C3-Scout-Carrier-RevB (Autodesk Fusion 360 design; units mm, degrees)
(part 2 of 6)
sketch "Socket solder tails profiles" plane through (0, 0, -3.2) normal (0, 0, 1) x axis (1, 0, 0)
  line L1 (-3.56, -9.14) -> (-4.06, -9.14)
  line L2 (-3.56, -8.64) -> (-3.56, -9.14)
  line L3 (-4.06, -8.64) -> (-3.56, -8.64)
  line L4 (-4.06, -9.14) -> (-4.06, -8.64)
  line L5 (-3.56, -6.6) -> (-4.06, -6.6)
  line L6 (-3.56, -6.1) -> (-3.56, -6.6)
  line L7 (-4.06, -6.1) -> (-3.56, -6.1)
  line L8 (-4.06, -6.6) -> (-4.06, -6.1)
  line L9 (-3.56, -4.06) -> (-4.06, -4.06)
  line L10 (-3.56, -3.56) -> (-3.56, -4.06)
  line L11 (-4.06, -3.56) -> (-3.56, -3.56)
  line L12 (-4.06, -4.06) -> (-4.06, -3.56)
  line L13 (-3.56, -1.52) -> (-4.06, -1.52)
  line L14 (-3.56, -1.02) -> (-3.56, -1.52)
  line L15 (-4.06, -1.02) -> (-3.56, -1.02)
  line L16 (-4.06, -1.52) -> (-4.06, -1.02)
  line L17 (-3.56, 1.02) -> (-4.06, 1.02)
  line L18 (-3.56, 1.52) -> (-3.56, 1.02)
  line L19 (-4.06, 1.52) -> (-3.56, 1.52)
  line L20 (-4.06, 1.02) -> (-4.06, 1.52)
  line L21 (-3.56, 3.56) -> (-4.06, 3.56)
  line L22 (-3.56, 4.06) -> (-3.56, 3.56)
  line L23 (-4.06, 4.06) -> (-3.56, 4.06)
  line L24 (-4.06, 3.56) -> (-4.06, 4.06)
  line L25 (-3.56, 6.1) -> (-4.06, 6.1)
  line L26 (-3.56, 6.6) -> (-3.56, 6.1)
  line L27 (-4.06, 6.6) -> (-3.56, 6.6)
  line L28 (-4.06, 6.1) -> (-4.06, 6.6)
  line L29 (-3.56, 8.64) -> (-4.06, 8.64)
  line L30 (-3.56, 9.14) -> (-3.56, 8.64)
  line L31 (-4.06, 9.14) -> (-3.56, 9.14)
  line L32 (-4.06, 8.64) -> (-4.06, 9.14)
  line L33 (4.06, -9.14) -> (3.56, -9.14)
  line L34 (4.06, -8.64) -> (4.06, -9.14)
  line L35 (3.56, -8.64) -> (4.06, -8.64)
  line L36 (3.56, -9.14) -> (3.56, -8.64)
  line L37 (4.06, -6.6) -> (3.56, -6.6)
  line L38 (4.06, -6.1) -> (4.06, -6.6)
  line L39 (3.56, -6.1) -> (4.06, -6.1)
  line L40 (3.56, -6.6) -> (3.56, -6.1)
  line L41 (4.06, -4.06) -> (3.56, -4.06)
  line L42 (4.06, -3.56) -> (4.06, -4.06)
  line L43 (3.56, -3.56) -> (4.06, -3.56)
  line L44 (3.56, -4.06) -> (3.56, -3.56)
  line L45 (4.06, -1.52) -> (3.56, -1.52)
  line L46 (4.06, -1.02) -> (4.06, -1.52)
  line L47 (3.56, -1.02) -> (4.06, -1.02)
  line L48 (3.56, -1.52) -> (3.56, -1.02)
  line L49 (4.06, 1.02) -> (3.56, 1.02)
  line L50 (4.06, 1.52) -> (4.06, 1.02)
  line L51 (3.56, 1.52) -> (4.06, 1.52)
  line L52 (3.56, 1.02) -> (3.56, 1.52)
  line L53 (4.06, 3.56) -> (3.56, 3.56)
  line L54 (4.06, 4.06) -> (4.06, 3.56)
  line L55 (3.56, 4.06) -> (4.06, 4.06)
  line L56 (3.56, 3.56) -> (3.56, 4.06)
  line L57 (4.06, 6.1) -> (3.56, 6.1)
  line L58 (4.06, 6.6) -> (4.06, 6.1)
  line L59 (3.56, 6.6) -> (4.06, 6.6)
  line L60 (3.56, 6.1) -> (3.56, 6.6)
  line L61 (4.06, 8.64) -> (3.56, 8.64)
  line L62 (4.06, 9.14) -> (4.06, 8.64)
  line L63 (3.56, 9.14) -> (4.06, 9.14)
  line L64 (3.56, 8.64) -> (3.56, 9.14)
extrude "Extrude5" new body sketch "Socket solder tails profiles" along normal blind 3.3
work_plane "WorkPlane1" AlongDistance 0.8 ExtraOffset 0
sketch "L293D molded body profile" plane through (0, 0, 0.8) normal (0, 0, 1) x axis (1, 0, 0)
  line L1 (3.2, -9.8) -> (-3.2, -9.8)
  line L2 (3.2, 9.8) -> (3.2, -9.8)
  line L3 (-3.2, 9.8) -> (3.2, 9.8)
  line L4 (-3.2, -9.8) -> (-3.2, 9.8)
extrude "Extrude1" new body sketch "L293D molded body profile" along normal blind 3.6
work_plane "WorkPlane2" AlongDistance 3.7 ExtraOffset 0
sketch "Orientation notch profile" plane through (0, 0, 3.7) normal (0, 0, 1) x axis (1, 0, 0)
  circle C1 centre (0, 9.8) radius 1.1
extrude "Extrude2" cut sketch "Orientation notch profile" along normal blind 0.7
work_plane "WorkPlane3" AlongDistance 4.4 ExtraOffset 0
sketch "Pin one dot profile" plane through (0, 0, 4.4) normal (0, 0, 1) x axis (1, 0, 0)
  circle C1 centre (-2.1, 7.8) radius 0.38
extrude "Extrude3" new body sketch "Pin one dot profile" along normal blind 0.025
work_plane "WorkPlane4" AlongDistance -2.5 ExtraOffset 0
sketch "DIP vertical leads profiles" plane through (0, 0, -2.5) normal (0, 0, 1) x axis (1, 0, 0)
  line L1 (-3.61, -9.14) -> (-4.01, -9.14)
  line L2 (-3.61, -8.64) -> (-3.61, -9.14)
  line L3 (-4.01, -8.64) -> (-3.61, -8.64)
  line L4 (-4.01, -9.14) -> (-4.01, -8.64)
  line L5 (-3.61, -6.6) -> (-4.01, -6.6)
  line L6 (-3.61, -6.1) -> (-3.61, -6.6)
  line L7 (-4.01, -6.1) -> (-3.61, -6.1)
  line L8 (-4.01, -6.6) -> (-4.01, -6.1)
  line L9 (-3.61, -4.06) -> (-4.01, -4.06)
  line L10 (-3.61, -3.56) -> (-3.61, -4.06)
  line L11 (-4.01, -3.56) -> (-3.61, -3.56)
  line L12 (-4.01, -4.06) -> (-4.01, -3.56)
  line L13 (-3.61, -1.52) -> (-4.01, -1.52)
  line L14 (-3.61, -1.02) -> (-3.61, -1.52)
  line L15 (-4.01, -1.02) -> (-3.61, -1.02)
  line L16 (-4.01, -1.52) -> (-4.01, -1.02)
  line L17 (-3.61, 1.02) -> (-4.01, 1.02)
  line L18 (-3.61, 1.52) -> (-3.61, 1.02)
  line L19 (-4.01, 1.52) -> (-3.61, 1.52)
  line L20 (-4.01, 1.02) -> (-4.01, 1.52)
  line L21 (-3.61, 3.56) -> (-4.01, 3.56)
  line L22 (-3.61, 4.06) -> (-3.61, 3.56)
  line L23 (-4.01, 4.06) -> (-3.61, 4.06)
  line L24 (-4.01, 3.56) -> (-4.01, 4.06)
  line L25 (-3.61, 6.1) -> (-4.01, 6.1)
  line L26 (-3.61, 6.6) -> (-3.61, 6.1)
  line L27 (-4.01, 6.6) -> (-3.61, 6.6)
  line L28 (-4.01, 6.1) -> (-4.01, 6.6)
  line L29 (-3.61, 8.64) -> (-4.01, 8.64)
  line L30 (-3.61, 9.14) -> (-3.61, 8.64)
  line L31 (-4.01, 9.14) -> (-3.61, 9.14)
  line L32 (-4.01, 8.64) -> (-4.01, 9.14)
  line L33 (4.01, -9.14) -> (3.61, -9.14)
  line L34 (4.01, -8.64) -> (4.01, -9.14)
  line L35 (3.61, -8.64) -> (4.01, -8.64)
  line L36 (3.61, -9.14) -> (3.61, -8.64)
  line L37 (4.01, -6.6) -> (3.61, -6.6)
  line L38 (4.01, -6.1) -> (4.01, -6.6)
  line L39 (3.61, -6.1) -> (4.01, -6.1)
  line L40 (3.61, -6.6) -> (3.61, -6.1)
  line L41 (4.01, -4.06) -> (3.61, -4.06)
  line L42 (4.01, -3.56) -> (4.01, -4.06)
  line L43 (3.61, -3.56) -> (4.01, -3.56)
  line L44 (3.61, -4.06) -> (3.61, -3.56)
  line L45 (4.01, -1.52) -> (3.61, -1.52)
  line L46 (4.01, -1.02) -> (4.01, -1.52)
  line L47 (3.61, -1.02) -> (4.01, -1.02)
  line L48 (3.61, -1.52) -> (3.61, -1.02)
  line L49 (4.01, 1.02) -> (3.61, 1.02)
  line L50 (4.01, 1.52) -> (4.01, 1.02)
  line L51 (3.61, 1.52) -> (4.01, 1.52)
  line L52 (3.61, 1.02) -> (3.61, 1.52)
  line L53 (4.01, 3.56) -> (3.61, 3.56)
  line L54 (4.01, 4.06) -> (4.01, 3.56)
  line L55 (3.61, 4.06) -> (4.01, 4.06)
  line L56 (3.61, 3.56) -> (3.61, 4.06)
  line L57 (4.01, 6.1) -> (3.61, 6.1)
  line L58 (4.01, 6.6) -> (4.01, 6.1)
  line L59 (3.61, 6.6) -> (4.01, 6.6)
  line L60 (3.61, 6.1) -> (3.61, 6.6)
  line L61 (4.01, 8.64) -> (3.61, 8.64)
  line L62 (4.01, 9.14) -> (4.01, 8.64)
  line L63 (3.61, 9.14) -> (4.01, 9.14)
  line L64 (3.61, 8.64) -> (3.61, 9.14)
extrude "Extrude4" new body sketch "DIP vertical leads profiles" along normal blind 4.3
work_plane "WorkPlane5" AlongDistance 1.5 ExtraOffset 0
sketch "DIP lead shoulders profiles" plane through (0, 0, 1.5) normal (0, 0, 1) x axis (1, 0, 0)
  line L1 (-2.7, -9.14) -> (-4.01, -9.14)
  line L2 (-2.7, -8.64) -> (-2.7, -9.14)
  line L3 (-4.01, -8.64) -> (-2.7, -8.64)
  line L4 (-4.01, -9.14) -> (-4.01, -8.64)
  line L5 (-2.7, -6.6) -> (-4.01, -6.6)
  line L6 (-2.7, -6.1) -> (-2.7, -6.6)
  line L7 (-4.01, -6.1) -> (-2.7, -6.1)
  line L8 (-4.01, -6.6) -> (-4.01, -6.1)
  line L9 (-2.7, -4.06) -> (-4.01, -4.06)
  line L10 (-2.7, -3.56) -> (-2.7, -4.06)
  line L11 (-4.01, -3.56) -> (-2.7, -3.56)
  line L12 (-4.01, -4.06) -> (-4.01, -3.56)
  line L13 (-2.7, -1.52) -> (-4.01, -1.52)
  line L14 (-2.7, -1.02) -> (-2.7, -1.52)
  line L15 (-4.01, -1.02) -> (-2.7, -1.02)
  line L16 (-4.01, -1.52) -> (-4.01, -1.02)
  line L17 (-2.7, 1.02) -> (-4.01, 1.02)
  line L18 (-2.7, 1.52) -> (-2.7, 1.02)
  line L19 (-4.01, 1.52) -> (-2.7, 1.52)
  line L20 (-4.01, 1.02) -> (-4.01, 1.52)
  line L21 (-2.7, 3.56) -> (-4.01, 3.56)
  line L22 (-2.7, 4.06) -> (-2.7, 3.56)
  line L23 (-4.01, 4.06) -> (-2.7, 4.06)
  line L24 (-4.01, 3.56) -> (-4.01, 4.06)
  line L25 (-2.7, 6.1) -> (-4.01, 6.1)
  line L26 (-2.7, 6.6) -> (-2.7, 6.1)
  line L27 (-4.01, 6.6) -> (-2.7, 6.6)
  line L28 (-4.01, 6.1) -> (-4.01, 6.6)
  line L29 (-2.7, 8.64) -> (-4.01, 8.64)
  line L30 (-2.7, 9.14) -> (-2.7, 8.64)
  line L31 (-4.01, 9.14) -> (-2.7, 9.14)
  line L32 (-4.01, 8.64) -> (-4.01, 9.14)
  line L33 (4.01, -9.14) -> (2.7, -9.14)
  line L34 (4.01, -8.64) -> (4.01, -9.14)
  line L35 (2.7, -8.64) -> (4.01, -8.64)
  line L36 (2.7, -9.14) -> (2.7, -8.64)
  line L37 (4.01, -6.6) -> (2.7, -6.6)
  line L38 (4.01, -6.1) -> (4.01, -6.6)
  line L39 (2.7, -6.1) -> (4.01, -6.1)
  line L40 (2.7, -6.6) -> (2.7, -6.1)
  line L41 (4.01, -4.06) -> (2.7, -4.06)
  line L42 (4.01, -3.56) -> (4.01, -4.06)
  line L43 (2.7, -3.56) -> (4.01, -3.56)
  line L44 (2.7, -4.06) -> (2.7, -3.56)
  line L45 (4.01, -1.52) -> (2.7, -1.52)
  line L46 (4.01, -1.02) -> (4.01, -1.52)
  line L47 (2.7, -1.02) -> (4.01, -1.02)
  line L48 (2.7, -1.52) -> (2.7, -1.02)
  line L49 (4.01, 1.02) -> (2.7, 1.02)
  line L50 (4.01, 1.52) -> (4.01, 1.02)
  line L51 (2.7, 1.52) -> (4.01, 1.52)
  line L52 (2.7, 1.02) -> (2.7, 1.52)
  line L53 (4.01, 3.56) -> (2.7, 3.56)
  line L54 (4.01, 4.06) -> (4.01, 3.56)
  line L55 (2.7, 4.06) -> (4.01, 4.06)
  line L56 (2.7, 3.56) -> (2.7, 4.06)
  line L57 (4.01, 6.1) -> (2.7, 6.1)
  line L58 (4.01, 6.6) -> (4.01, 6.1)
  line L59 (2.7, 6.6) -> (4.01, 6.6)
  line L60 (2.7, 6.1) -> (2.7, 6.6)
  line L61 (4.01, 8.64) -> (2.7, 8.64)
  line L62 (4.01, 9.14) -> (4.01, 8.64)
  line L63 (2.7, 9.14) -> (4.01, 9.14)
  line L64 (2.7, 8.64) -> (2.7, 9.14)
extrude "Extrude5" new body sketch "DIP lead shoulders profiles" along normal blind 0.3
sketch "Holder floor profile" plane through (0, 0, 0) normal (0, 0, 1) x axis (1, 0, 0)
  line L1 (11, -39) -> (-11, -39)
  line L2 (11, 39) -> (11, -39)
  line L3 (-11, 39) -> (11, 39)
  line L4 (-11, -39) -> (-11, 39)
extrude "Extrude1" new body sketch "Holder floor profile" along normal blind 2
work_plane "WorkPlane1" AlongDistance 2 ExtraOffset 0
sketch "Holder side lip profile" plane through (0, 0, 2) normal (0, 0, 1) x axis (1, 0, 0)
  line L1 (-9.8, -39) -> (-11, -39)
  line L2 (-9.8, 39) -> (-9.8, -39)
  line L3 (-11, 39) -> (-9.8, 39)
  line L4 (-11, -39) -> (-11, 39)
extrude "Extrude2" add sketch "Holder side lip profile" along normal blind 3
work_plane "WorkPlane2" AlongDistance 2 ExtraOffset 0
sketch "Holder side lip profile (1)" plane through (0, 0, 2) normal (0, 0, 1) x axis (1, 0, 0)
  line L1 (11, -39) -> (9.8, -39)
  line L2 (11, 39) -> (11, -39)
  line L3 (9.8, 39) -> (11, 39)
  line L4 (9.8, -39) -> (9.8, 39)
extrude "Extrude3" add sketch "Holder side lip profile (1)" along normal blind 3
work_plane "WorkPlane3" AlongDistance 2 ExtraOffset 0
sketch "Holder end plate profile" plane through (0, 0, 2) normal (0, 0, 1) x axis (1, 0, 0)
  line L1 (11, -39) -> (-11, -39)
  line L2 (11, -37) -> (11, -39)
  line L3 (-11, -37) -> (11, -37)
  line L4 (-11, -39) -> (-11, -37)
extrude "Extrude4" add sketch "Holder end plate profile" along normal blind 10
work_plane "WorkPlane4" AlongDistance 2 ExtraOffset 0
sketch "Holder end plate profile (1)" plane through (0, 0, 2) normal (0, 0, 1) x axis (1, 0, 0)
  line L1 (11, 37) -> (-11, 37)
  line L2 (11, 39) -> (11, 37)
  line L3 (-11, 39) -> (11, 39)
  line L4 (-11, 37) -> (-11, 39)
extrude "Extrude5" add sketch "Holder end plate profile (1)" along normal blind 10
sketch "Cell shrink sleeve profile" plane through (0, 0, 0) normal (0, 0, 1) x axis (1, 0, 0)
  circle C1 centre (0, 0) radius 9.3
extrude "Extrude1" new body sketch "Cell shrink sleeve profile" along a picked direction blind 68.5
work_plane "WorkPlane1" AlongDistance -0.03 ExtraOffset 0
sketch "Negative contact profile" plane through (0, 0, -0.03) normal (0, 0, 1) x axis (1, 0, 0)
  circle C1 centre (0, 0) radius 8.4
extrude "Extrude2" new body sketch "Negative contact profile" along a picked direction blind 0.03
work_plane "WorkPlane2" AlongDistance 68.5 ExtraOffset 0
sketch "Positive shoulder profile" plane through (0, 0, 68.5) normal (0, 0, 1) x axis (1, 0, 0)
  circle C1 centre (0, 0) radius 8.6
extrude "Extrude3" new body sketch "Positive shoulder profile" along a picked direction blind 0.25
work_plane "WorkPlane3" AlongDistance 68.75 ExtraOffset 0
sketch "Positive button profile" plane through (0, 0, 68.75) normal (0, 0, 1) x axis (1, 0, 0)
  circle C1 centre (0, 0) radius 3
extrude "Extrude4" new body sketch "Positive button profile" along a picked direction blind 0.75
sketch "Contact plate profile" plane through (0, 0, 0) normal (0, 0, 1) x axis (1, 0, 0)
  line L1 (4, -5) -> (-4, -5)
  line L2 (4, 5) -> (4, -5)
  line L3 (-4, 5) -> (4, 5)
  line L4 (-4, -5) -> (-4, 5)
extrude "Extrude1" new body sketch "Contact plate profile" along a picked direction blind 0.3
work_plane "WorkPlane1" AlongDistance 0.3 ExtraOffset 0
sketch "Spring ring" plane through (0, 0, 0.3) normal (0, 0, 1) x axis (1, 0, 0)
  circle C1 centre (0, 0) radius 3.5
  circle C2 centre (0, 0) radius 3.25
extrude "Extrude2" new body sketch "Spring ring" along a picked direction blind 0.25
work_plane "WorkPlane2" AlongDistance 0.8 ExtraOffset 0
sketch "Spring ring (1)" plane through (0, 0, 0.8) normal (0, 0, 1) x axis (1, 0, 0)
  circle C1 centre (0, 0) radius 3.1
  circle C2 centre (0, 0) radius 2.85
extrude "Extrude3" new body sketch "Spring ring (1)" along a picked direction blind 0.25
work_plane "WorkPlane3" AlongDistance 1.3 ExtraOffset 0
sketch "Spring ring (2)" plane through (0, 0, 1.3) normal (0, 0, 1) x axis (1, 0, 0)
  circle C1 centre (0, 0) radius 2.7
  circle C2 centre (0, 0) radius 2.45
extrude "Extrude4" new body sketch "Spring ring (2)" along a picked direction blind 0.25
place_component sketch "Contact plate profile"
sketch "Contact plate profile" plane through (0, 0, 0) normal (0, 0, 1) x axis (1, 0, 0)
  line L1 (4, -5) -> (-4, -5)
  line L2 (4, 5) -> (4, -5)
  line L3 (-4, 5) -> (4, 5)
  line L4 (-4, -5) -> (-4, 5)
extrude "Extrude1" new body sketch "Contact plate profile" along a picked direction blind 0.3
base_feature "Base Feature1"
base_feature "Base Feature1"
base_feature "Base Feature1"
position "Position2"
copy_paste "CopyPaste2"
copy_paste "CopyPaste3"
remove_instance "RemoveInstance1"
work_plane "WorkPlane1" AlongDistance -3.4 ExtraOffset 0
sketch "M2.5 x18 clamp shafts profiles" plane through (0, 0, -3.4) normal (0, 0, 1) x axis (1, 0, 0)
  circle C1 centre (-26, -42) radius 1.25
  circle C2 centre (-26, -22) radius 1.25
  circle C3 centre (26, -42) radius 1.25
  circle C4 centre (26, -22) radius 1.25
extrude "Extrude1" new body sketch "M2.5 x18 clamp shafts profiles" along normal blind 18
work_plane "WorkPlane2" AlongDistance 14.6 ExtraOffset 0
sketch "M2.5 clamp heads profiles" plane through (0, 0, 14.6) normal (0, 0, 1) x axis (1, 0, 0)
  circle C1 centre (-26, -42) radius 2.35
  circle C2 centre (-26, -22) radius 2.35
  circle C3 centre (26, -42) radius 2.35
  circle C4 centre (26, -22) radius 2.35
extrude "Extrude2" new body sketch "M2.5 clamp heads profiles" along normal blind 1.2
work_plane "WorkPlane3" AlongDistance -4 ExtraOffset 0
sketch "M3 x10 bumper shafts profiles" plane through (0, 0, -4) normal (0, 0, 1) x axis (1, 0, 0)
  circle C1 centre (-28, -49) radius 1.5
  circle C2 centre (28, -49) radius 1.5
extrude "Extrude3" new body sketch "M3 x10 bumper shafts profiles" along normal blind 10
work_plane "WorkPlane4" AlongDistance 6 ExtraOffset 0
sketch "M3 bumper heads profiles" plane through (0, 0, 6) normal (0, 0, 1) x axis (1, 0, 0)
  circle C1 centre (-28, -49) radius 2.7
  circle C2 centre (28, -49) radius 2.7
extrude "Extrude4" new body sketch "M3 bumper heads profiles" along normal blind 2.2
work_plane "WorkPlane5" AlongDistance -7 ExtraOffset 0
sketch "M3 x10 skid shafts profiles" plane through (0, 0, -7) normal (0, 0, 1) x axis (1, 0, 0)
  circle C1 centre (2, 52) radius 1.5
  circle C2 centre (2, 60) radius 1.5
extrude "Extrude5" new body sketch "M3 x10 skid shafts profiles" along normal blind 10
work_plane "WorkPlane6" AlongDistance 3 ExtraOffset 0
sketch "M3 skid heads profiles" plane through (0, 0, 3) normal (0, 0, 1) x axis (1, 0, 0)
  circle C1 centre (2, 52) radius 2.7
  circle C2 centre (2, 60) radius 2.7
extrude "Extrude6" new body sketch "M3 skid heads profiles" along normal blind 2.2
work_plane "WorkPlane7" AlongDistance 15.2 ExtraOffset 0
sketch "Clamp hex drives profiles" plane through (0, 0, 15.2) normal (0, 0, 1) x axis (1, 0, 0)
  line L1 (-25.5, -41.134) -> (-25, -42)
  line L2 (-26.5, -41.134) -> (-25.5, -41.134)
  line L3 (-27, -42) -> (-26.5, -41.134)
  line L4 (-26.5, -42.866) -> (-27, -42)
  line L5 (-25.5, -42.866) -> (-26.5, -42.866)
  line L6 (-25, -42) -> (-25.5, -42.866)
  line L7 (-25.5, -21.134) -> (-25, -22)
  line L8 (-26.5, -21.134) -> (-25.5, -21.134)
  line L9 (-27, -22) -> (-26.5, -21.134)
  line L10 (-26.5, -22.866) -> (-27, -22)
  line L11 (-25.5, -22.866) -> (-26.5, -22.866)
  line L12 (-25, -22) -> (-25.5, -22.866)
  line L13 (26.5, -41.134) -> (27, -42)
  line L14 (25.5, -41.134) -> (26.5, -41.134)
  line L15 (25, -42) -> (25.5, -41.134)
  line L16 (25.5, -42.866) -> (25, -42)
  line L17 (26.5, -42.866) -> (25.5, -42.866)
  line L18 (27, -42) -> (26.5, -42.866)
  line L19 (26.5, -21.134) -> (27, -22)
  line L20 (25.5, -21.134) -> (26.5, -21.134)
  line L21 (25, -22) -> (25.5, -21.134)
  line L22 (25.5, -22.866) -> (25, -22)
  line L23 (26.5, -22.866) -> (25.5, -22.866)
  line L24 (27, -22) -> (26.5, -22.866)
extrude "Extrude7" cut sketch "Clamp hex drives profiles" along normal blind 0.6
work_plane "WorkPlane8" AlongDistance 7.1 ExtraOffset 0
sketch "Bumper hex drives profiles" plane through (0, 0, 7.1) normal (0, 0, 1) x axis (1, 0, 0)
  line L1 (-27.3, -47.7876) -> (-26.6, -49)
  line L2 (-28.7, -47.7876) -> (-27.3, -47.7876)
  line L3 (-29.4, -49) -> (-28.7, -47.7876)
  line L4 (-28.7, -50.2124) -> (-29.4, -49)
  line L5 (-27.3, -50.2124) -> (-28.7, -50.2124)
  line L6 (-26.6, -49) -> (-27.3, -50.2124)
  line L7 (28.7, -47.7876) -> (29.4, -49)
  line L8 (27.3, -47.7876) -> (28.7, -47.7876)
  line L9 (26.6, -49) -> (27.3, -47.7876)
  line L10 (27.3, -50.2124) -> (26.6, -49)
  line L11 (28.7, -50.2124) -> (27.3, -50.2124)
  line L12 (29.4, -49) -> (28.7, -50.2124)
extrude "Extrude8" cut sketch "Bumper hex drives profiles" along normal blind 1.1
work_plane "WorkPlane9" AlongDistance 4.1 ExtraOffset 0
sketch "Skid hex drives profiles" plane through (0, 0, 4.1) normal (0, 0, 1) x axis (1, 0, 0)
  line L1 (2.7, 53.2124) -> (3.4, 52)
  line L2 (1.3, 53.2124) -> (2.7, 53.2124)
  line L3 (0.6, 52) -> (1.3, 53.2124)
  line L4 (1.3, 50.7876) -> (0.6, 52)
  line L5 (2.7, 50.7876) -> (1.3, 50.7876)
  line L6 (3.4, 52) -> (2.7, 50.7876)
  line L7 (2.7, 61.2124) -> (3.4, 60)
  line L8 (1.3, 61.2124) -> (2.7, 61.2124)
  line L9 (0.6, 60) -> (1.3, 61.2124)
  line L10 (1.3, 58.7876) -> (0.6, 60)
  line L11 (2.7, 58.7876) -> (1.3, 58.7876)
  line L12 (3.4, 60) -> (2.7, 58.7876)
extrude "Extrude9" cut sketch "Skid hex drives profiles" along normal blind 1.1
work_plane "WorkPlane1" AlongDistance -2.2 ExtraOffset 0
sketch "M2.5 nuts profiles" plane through (0, 0, -2.2) normal (0, 0, 1) x axis (1, 0, 0)
  line L1 (-24.555, -39.4972) -> (-23.11, -42)
  line L2 (-27.445, -39.4972) -> (-24.555, -39.4972)
  line L3 (-28.89, -42) -> (-27.445, -39.4972)
  line L4 (-27.445, -44.5028) -> (-28.89, -42)
  line L5 (-24.555, -44.5028) -> (-27.445, -44.5028)
  line L6 (-23.11, -42) -> (-24.555, -44.5028)
  line L7 (-24.555, -19.4972) -> (-23.11, -22)
  line L8 (-27.445, -19.4972) -> (-24.555, -19.4972)
  line L9 (-28.89, -22) -> (-27.445, -19.4972)
  line L10 (-27.445, -24.5028) -> (-28.89, -22)
  line L11 (-24.555, -24.5028) -> (-27.445, -24.5028)
  line L12 (-23.11, -22) -> (-24.555, -24.5028)
  line L13 (27.445, -39.4972) -> (28.89, -42)
  line L14 (24.555, -39.4972) -> (27.445, -39.4972)
  line L15 (23.11, -42) -> (24.555, -39.4972)
  line L16 (24.555, -44.5028) -> (23.11, -42)
  line L17 (27.445, -44.5028) -> (24.555, -44.5028)
  line L18 (28.89, -42) -> (27.445, -44.5028)
  line L19 (27.445, -19.4972) -> (28.89, -22)
  line L20 (24.555, -19.4972) -> (27.445, -19.4972)
  line L21 (23.11, -22) -> (24.555, -19.4972)
  line L22 (24.555, -24.5028) -> (23.11, -22)
  line L23 (27.445, -24.5028) -> (24.555, -24.5028)
  line L24 (28.89, -22) -> (27.445, -24.5028)
extrude "Extrude1" new body sketch "M2.5 nuts profiles" along normal blind 2
work_plane "WorkPlane2" AlongDistance -2.2 ExtraOffset 0
sketch "M2.5 nuts bores profile" plane through (0, 0, -2.2) normal (0, 0, 1) x axis (1, 0, 0)
  circle C1 centre (-26, -42) radius 1.3
  circle C2 centre (-26, -22) radius 1.3
  circle C3 centre (26, -42) radius 1.3
  circle C4 centre (26, -22) radius 1.3
extrude "Extrude2" cut sketch "M2.5 nuts bores profile" along normal blind 2
work_plane "WorkPlane3" AlongDistance -2.6 ExtraOffset 0
sketch "M3 bumper nuts profiles" plane through (0, 0, -2.6) normal (0, 0, 1) x axis (1, 0, 0)
  line L1 (-26.41, -46.246) -> (-24.82, -49)
  line L2 (-29.59, -46.246) -> (-26.41, -46.246)
  line L3 (-31.18, -49) -> (-29.59, -46.246)
  line L4 (-29.59, -51.754) -> (-31.18, -49)
  line L5 (-26.41, -51.754) -> (-29.59, -51.754)
  line L6 (-24.82, -49) -> (-26.41, -51.754)
  line L7 (29.59, -46.246) -> (31.18, -49)
  line L8 (26.41, -46.246) -> (29.59, -46.246)
  line L9 (24.82, -49) -> (26.41, -46.246)
  line L10 (26.41, -51.754) -> (24.82, -49)
  line L11 (29.59, -51.754) -> (26.41, -51.754)
  line L12 (31.18, -49) -> (29.59, -51.754)
extrude "Extrude3" new body sketch "M3 bumper nuts profiles" along normal blind 2.4
work_plane "WorkPlane4" AlongDistance -2.6 ExtraOffset 0
sketch "M3 bumper nuts bores profile" plane through (0, 0, -2.6) normal (0, 0, 1) x axis (1, 0, 0)
  circle C1 centre (-28, -49) radius 1.55
  circle C2 centre (28, -49) radius 1.55
extrude "Extrude4" cut sketch "M3 bumper nuts bores profile" along normal blind 2.4
work_plane "WorkPlane5" AlongDistance -6.6 ExtraOffset 0
sketch "M3 skid nuts profiles" plane through (0, 0, -6.6) normal (0, 0, 1) x axis (1, 0, 0)
  line L1 (3.59, 54.754) -> (5.18, 52)
  line L2 (0.41, 54.754) -> (3.59, 54.754)
  line L3 (-1.18, 52) -> (0.41, 54.754)
  line L4 (0.41, 49.246) -> (-1.18, 52)
  line L5 (3.59, 49.246) -> (0.41, 49.246)
  line L6 (5.18, 52) -> (3.59, 49.246)
  line L7 (3.59, 62.754) -> (5.18, 60)
  line L8 (0.41, 62.754) -> (3.59, 62.754)
  line L9 (-1.18, 60) -> (0.41, 62.754)
  line L10 (0.41, 57.246) -> (-1.18, 60)
  line L11 (3.59, 57.246) -> (0.41, 57.246)
  line L12 (5.18, 60) -> (3.59, 57.246)
extrude "Extrude5" new body sketch "M3 skid nuts profiles" along normal blind 2.4
work_plane "WorkPlane6" AlongDistance -6.6 ExtraOffset 0
sketch "M3 skid nuts bores profile" plane through (0, 0, -6.6) normal (0, 0, 1) x axis (1, 0, 0)
  circle C1 centre (2, 52) radius 1.55
  circle C2 centre (2, 60) radius 1.55
extrude "Extrude6" cut sketch "M3 skid nuts bores profile" no distance stored
work_plane "WorkPlane1" AlongDistance 4.5 ExtraOffset 0
sketch "Foam strip profile" plane through (0, 0, 4.5) normal (0, 0, 1) x axis (1, 0, 0)
  line L1 (27, 42) -> (10, 42)
  line L2 (27, 44.5) -> (27, 42)
  line L3 (10, 44.5) -> (27, 44.5)
  line L4 (10, 42) -> (10, 44.5)
extrude "Extrude1" new body sketch "Foam strip profile" along normal blind 1.5
work_plane "WorkPlane2" AlongDistance 4.5 ExtraOffset 0
sketch "Foam strip profile (1)" plane through (0, 0, 4.5) normal (0, 0, 1) x axis (1, 0, 0)
  line L1 (27, 60) -> (10, 60)
  line L2 (27, 62.5) -> (27, 60)
  line L3 (10, 62.5) -> (27, 62.5)
  line L4 (10, 60) -> (10, 62.5)
extrude "Extrude2" new body sketch "Foam strip profile (1)" along normal blind 1.5
work_plane "WorkPlane3" AlongDistance 4.5 ExtraOffset 0
sketch "Foam strip profile (2)" plane through (0, 0, 4.5) normal (0, 0, 1) x axis (1, 0, 0)
  line L1 (25.8, 17.4) -> (11.2, 17.4)
  line L2 (25.8, 18) -> (25.8, 17.4)
  line L3 (11.2, 18) -> (25.8, 18)
  line L4 (11.2, 17.4) -> (11.2, 18)
extrude "Extrude3" new body sketch "Foam strip profile (2)" along normal blind 1.5
work_plane "WorkPlane4" AlongDistance 4.5 ExtraOffset 0
sketch "Foam strip profile (3)" plane through (0, 0, 4.5) normal (0, 0, 1) x axis (1, 0, 0)
  line L1 (25.8, 32) -> (11.2, 32)
  line L2 (25.8, 32.6) -> (25.8, 32)
  line L3 (11.2, 32.6) -> (25.8, 32.6)
  line L4 (11.2, 32) -> (11.2, 32.6)
extrude "Extrude4" new body sketch "Foam strip profile (3)" along normal blind 1.5
fillet "Fillet1" radius 0.6
fillet "Fillet1" radius 0.6
work_plane "WorkPlane23" AlongDistance 3 ExtraOffset 0
sketch "SCOUT marking" plane through (0, 0, 3) normal (0, 0, 1) x axis (1, 0, 0)
  dimension "d490" = 2.8
extrude "Extrude43" cut sketch "SCOUT marking" against normal blind 0.35
work_plane "WorkPlane6" AlongDistance 4.4 ExtraOffset 0
sketch "L293D marking" plane through (0, 0, 4.4) normal (0, 0, 1) x axis (1, 0, 0)
  dimension "d496" = 1.25
  dimension "d497" = "'L293D'"
extrude "Extrude6" new body sketch "L293D marking" along normal blind 0.025
place_component sketch "Retention strap cross section"
sketch "Retention strap cross section" plane through (0, 0, 0) normal (0, 0, 1) x axis (1, 0, 0)
  line L1 (16.7, -0.8) -> (-16.3, -0.8)
  line L2 (16.7, 8) -> (16.7, -0.8)
  line L3 (10.2, 14.7) -> (16.7, 8)
  line L4 (10.1127, 16.0314) -> (10.2, 14.7)
  line L5 (9.8524, 17.34) -> (10.1127, 16.0314)
  line L6 (9.4236, 18.6034) -> (9.8524, 17.34)
  line L7 (8.8335, 19.8) -> (9.4236, 18.6034)
  line L8 (8.0922, 20.9094) -> (8.8335, 19.8)
  line L9 (7.2125, 21.9125) -> (8.0922, 20.9094)
  line L10 (6.2094, 22.7922) -> (7.2125, 21.9125)
  line L11 (5.1, 23.5335) -> (6.2094, 22.7922)
  line L12 (3.9034, 24.1236) -> (5.1, 23.5335)
  line L13 (2.64, 24.5524) -> (3.9034, 24.1236)
  line L14 (1.3314, 24.8127) -> (2.64, 24.5524)
  line L15 (0, 24.9) -> (1.3314, 24.8127)
  line L16 (-1.3314, 24.8127) -> (0, 24.9)
  line L17 (-2.64, 24.5524) -> (-1.3314, 24.8127)
  line L18 (-3.9034, 24.1236) -> (-2.64, 24.5524)
  line L19 (-5.1, 23.5335) -> (-3.9034, 24.1236)
  line L20 (-6.2094, 22.7922) -> (-5.1, 23.5335)
  line L21 (-7.2125, 21.9125) -> (-6.2094, 22.7922)
  line L22 (-8.0922, 20.9094) -> (-7.2125, 21.9125)
  line L23 (-8.8335, 19.8) -> (-8.0922, 20.9094)
  line L24 (-9.4236, 18.6034) -> (-8.8335, 19.8)
  line L25 (-9.8524, 17.34) -> (-9.4236, 18.6034)
  line L26 (-10.1127, 16.0314) -> (-9.8524, 17.34)
  line L27 (-10.2, 14.7) -> (-10.1127, 16.0314)
  line L28 (-16.3, 8) -> (-10.2, 14.7)
  line L29 (-16.3, -0.8) -> (-16.3, 8)
  line L30 (16, 0) -> (-15.6, 0)
  line L31 (16, 7.8) -> (16, 0)
  line L32 (9.5, 14.7) -> (16, 7.8)
  line L33 (9.4187, 15.94) -> (9.5, 14.7)
  line L34 (9.1763, 17.1588) -> (9.4187, 15.94)
  line L35 (8.7769, 18.3355) -> (9.1763, 17.1588)
  line L36 (8.2272, 19.45) -> (8.7769, 18.3355)
  line L37 (7.5369, 20.4832) -> (8.2272, 19.45)
  line L38 (6.7175, 21.4175) -> (7.5369, 20.4832)
  line L39 (5.7832, 22.2369) -> (6.7175, 21.4175)
  line L40 (4.75, 22.9272) -> (5.7832, 22.2369)
  line L41 (3.6355, 23.4769) -> (4.75, 22.9272)
  line L42 (2.4588, 23.8763) -> (3.6355, 23.4769)
  line L43 (1.24, 24.1187) -> (2.4588, 23.8763)
  line L44 (0, 24.2) -> (1.24, 24.1187)
  line L45 (-1.24, 24.1187) -> (0, 24.2)
  line L46 (-2.4588, 23.8763) -> (-1.24, 24.1187)
  line L47 (-3.6355, 23.4769) -> (-2.4588, 23.8763)
  line L48 (-4.75, 22.9272) -> (-3.6355, 23.4769)
  line L49 (-5.7832, 22.2369) -> (-4.75, 22.9272)
  line L50 (-6.7175, 21.4175) -> (-5.7832, 22.2369)
  line L51 (-7.5369, 20.4832) -> (-6.7175, 21.4175)
  line L52 (-8.2272, 19.45) -> (-7.5369, 20.4832)
  line L53 (-8.7769, 18.3355) -> (-8.2272, 19.45)
  line L54 (-9.1763, 17.1588) -> (-8.7769, 18.3355)
  line L55 (-9.4187, 15.94) -> (-9.1763, 17.1588)
  line L56 (-9.5, 14.7) -> (-9.4187, 15.94)
  line L57 (-15.6, 7.8) -> (-9.5, 14.7)
  line L58 (-15.6, 0) -> (-15.6, 7.8)
extrude "Extrude1" new body sketch "Retention strap cross section" along a picked direction blind 8
place_component sketch "Retention strap cross section"
sketch "Retention strap cross section" plane through (0, 0, 0) normal (0, 0, 1) x axis (1, 0, 0)
  line L1 (16.7, -0.8) -> (-16.3, -0.8)
  line L2 (16.7, 8) -> (16.7, -0.8)
  line L3 (10.2, 14.7) -> (16.7, 8)
  line L4 (10.1127, 16.0314) -> (10.2, 14.7)
  line L5 (9.8524, 17.34) -> (10.1127, 16.0314)
  line L6 (9.4236, 18.6034) -> (9.8524, 17.34)
  line L7 (8.8335, 19.8) -> (9.4236, 18.6034)
  line L8 (8.0922, 20.9094) -> (8.8335, 19.8)
  line L9 (7.2125, 21.9125) -> (8.0922, 20.9094)
  line L10 (6.2094, 22.7922) -> (7.2125, 21.9125)
  line L11 (5.1, 23.5335) -> (6.2094, 22.7922)
  line L12 (3.9034, 24.1236) -> (5.1, 23.5335)
  line L13 (2.64, 24.5524) -> (3.9034, 24.1236)
  line L14 (1.3314, 24.8127) -> (2.64, 24.5524)
  line L15 (0, 24.9) -> (1.3314, 24.8127)
  line L16 (-1.3314, 24.8127) -> (0, 24.9)
  line L17 (-2.64, 24.5524) -> (-1.3314, 24.8127)
  line L18 (-3.9034, 24.1236) -> (-2.64, 24.5524)
  line L19 (-5.1, 23.5335) -> (-3.9034, 24.1236)
  line L20 (-6.2094, 22.7922) -> (-5.1, 23.5335)
  line L21 (-7.2125, 21.9125) -> (-6.2094, 22.7922)
  line L22 (-8.0922, 20.9094) -> (-7.2125, 21.9125)
  line L23 (-8.8335, 19.8) -> (-8.0922, 20.9094)
  line L24 (-9.4236, 18.6034) -> (-8.8335, 19.8)
  line L25 (-9.8524, 17.34) -> (-9.4236, 18.6034)
  line L26 (-10.1127, 16.0314) -> (-9.8524, 17.34)
  line L27 (-10.2, 14.7) -> (-10.1127, 16.0314)
  line L28 (-16.3, 8) -> (-10.2, 14.7)
  line L29 (-16.3, -0.8) -> (-16.3, 8)
  line L30 (16, 0) -> (-15.6, 0)
  line L31 (16, 7.8) -> (16, 0)
  line L32 (9.5, 14.7) -> (16, 7.8)
  line L33 (9.4187, 15.94) -> (9.5, 14.7)
  line L34 (9.1763, 17.1588) -> (9.4187, 15.94)
  line L35 (8.7769, 18.3355) -> (9.1763, 17.1588)
  line L36 (8.2272, 19.45) -> (8.7769, 18.3355)
  line L37 (7.5369, 20.4832) -> (8.2272, 19.45)
  line L38 (6.7175, 21.4175) -> (7.5369, 20.4832)
  line L39 (5.7832, 22.2369) -> (6.7175, 21.4175)
  line L40 (4.75, 22.9272) -> (5.7832, 22.2369)
  line L41 (3.6355, 23.4769) -> (4.75, 22.9272)
  line L42 (2.4588, 23.8763) -> (3.6355, 23.4769)
  line L43 (1.24, 24.1187) -> (2.4588, 23.8763)
  line L44 (0, 24.2) -> (1.24, 24.1187)
  line L45 (-1.24, 24.1187) -> (0, 24.2)
  line L46 (-2.4588, 23.8763) -> (-1.24, 24.1187)
  line L47 (-3.6355, 23.4769) -> (-2.4588, 23.8763)
  line L48 (-4.75, 22.9272) -> (-3.6355, 23.4769)
  line L49 (-5.7832, 22.2369) -> (-4.75, 22.9272)
  line L50 (-6.7175, 21.4175) -> (-5.7832, 22.2369)
  line L51 (-7.5369, 20.4832) -> (-6.7175, 21.4175)
  line L52 (-8.2272, 19.45) -> (-7.5369, 20.4832)
  line L53 (-8.7769, 18.3355) -> (-8.2272, 19.45)
  line L54 (-9.1763, 17.1588) -> (-8.7769, 18.3355)
  line L55 (-9.4187, 15.94) -> (-9.1763, 17.1588)
  line L56 (-9.5, 14.7) -> (-9.4187, 15.94)
  line L57 (-15.6, 7.8) -> (-9.5, 14.7)
  line L58 (-15.6, 0) -> (-15.6, 7.8)
extrude "Extrude1" new body sketch "Retention strap cross section" along a picked direction blind 8
work_plane "WorkPlane4" AlongDistance 3 ExtraOffset 0
sketch "Recessed M3 bumper head clearance profile" plane through (0, 0, 3) normal (0, 0, 1) x axis (1, 0, 0)
  circle C1 centre (-28, -49) radius 2.9
  circle C2 centre (28, -49) radius 2.9
extrude "Extrude8" cut sketch "Recessed M3 bumper head clearance profile" along normal blind 3
position "Position3"
position "Position4"
extrude "Extrude7" cut sketch "Spine detail outline" against normal blind 0.7 (magnitude of "-( 0.7 mm )")
extrude "Extrude7" cut sketch "Spine detail outline" against normal blind 0.7 (magnitude of "-( 0.7 mm )")
sketch "Swept mounting tray outline" plane through (0, 0, 0) normal (0, 0, 1) x axis (1, 0, 0)
  line L1 (8.7, -51.4) -> (-8.7, -51.4)
  line L2 (10.2, -49) -> (8.7, -51.4)
  line L3 (14, -49) -> (10.2, -49)
  line L4 (16, -47) -> (14, -49)
  line L5 (16, -43) -> (16, -47)
  line L6 (14, -41) -> (16, -43)
  line L7 (10.2, -40) -> (14, -41)
  line L8 (10.2, -23) -> (10.2, -40)
  line L9 (8.2, -21.5) -> (10.2, -23)
  line L10 (-8.2, -21.5) -> (8.2, -21.5)
  line L11 (-10.2, -23) -> (-8.2, -21.5)
  line L12 (-10.2, -40) -> (-10.2, -23)
  line L13 (-14, -41) -> (-10.2, -40)
  line L14 (-16, -43) -> (-14, -41)
  line L15 (-16, -47) -> (-16, -43)
  line L16 (-14, -49) -> (-16, -47)
  line L17 (-10.2, -49) -> (-14, -49)
  line L18 (-8.7, -51.4) -> (-10.2, -49)
extrude "Extrude1" new body sketch "Swept mounting tray outline" along normal blind 1.8
work_plane "WorkPlane1" AlongDistance 1.8 ExtraOffset 0
sketch "Board edge guide profile" plane through (0, 0, 1.8) normal (0, 0, 1) x axis (1, 0, 0)
  line L1 (-8.7, -40) -> (-10.2, -40)
  line L2 (-8.7, -23) -> (-8.7, -40)
  line L3 (-10.2, -23) -> (-8.7, -23)
  line L4 (-10.2, -40) -> (-10.2, -23)
extrude "Extrude2" add sketch "Board edge guide profile" along normal blind 2.6
work_plane "WorkPlane2" AlongDistance 1.8 ExtraOffset 0
sketch "Board edge guide profile (1)" plane through (0, 0, 1.8) normal (0, 0, 1) x axis (1, 0, 0)
  line L1 (10.2, -40) -> (8.7, -40)
  line L2 (10.2, -23) -> (10.2, -40)
  line L3 (8.7, -23) -> (10.2, -23)
  line L4 (8.7, -40) -> (8.7, -23)
extrude "Extrude3" add sketch "Board edge guide profile (1)" along normal blind 2.6
work_plane "WorkPlane3" AlongDistance 1.8 ExtraOffset 0
sketch "Rear locating stop profile" plane through (0, 0, 1.8) normal (0, 0, 1) x axis (1, 0, 0)
  line L1 (8.7, -22.8) -> (-8.7, -22.8)
  line L2 (8.7, -21.5) -> (8.7, -22.8)
  line L3 (-8.7, -21.5) -> (8.7, -21.5)
  line L4 (-8.7, -22.8) -> (-8.7, -21.5)
extrude "Extrude4" add sketch "Rear locating stop profile" along normal blind 2.6
sketch "Cooling window profile" plane through (0, 0, 0) normal (0, 0, 1) x axis (1, 0, 0)
  line L1 (5.6, -42) -> (-5.6, -42)
  line L2 (5.6, -39) -> (5.6, -42)
  line L3 (-5.6, -39) -> (5.6, -39)
  line L4 (-5.6, -42) -> (-5.6, -39)
extrude "Extrude5" cut sketch "Cooling window profile" along normal blind 1.8
sketch "Cooling window profile (1)" plane through (0, 0, 0) normal (0, 0, 1) x axis (1, 0, 0)
  line L1 (5.6, -36) -> (-5.6, -36)
  line L2 (5.6, -33) -> (5.6, -36)
  line L3 (-5.6, -33) -> (5.6, -33)
  line L4 (-5.6, -36) -> (-5.6, -33)
extrude "Extrude6" cut sketch "Cooling window profile (1)" along normal blind 1.8
sketch "Existing chassis M3 interface profile" plane through (0, 0, 0) normal (0, 0, 1) x axis (1, 0, 0)
  circle C1 centre (-12, -45) radius 1.6
  circle C2 centre (12, -45) radius 1.6
extrude "Extrude7" cut sketch "Existing chassis M3 interface profile" along normal blind 1.8
work_plane "WorkPlane5" AlongDistance 2 ExtraOffset 0
sketch "Front USB-C cable clearance profile" plane through (0, 0, 2) normal (0, 0, 1) x axis (1, 0, 0)
  line L1 (7, -56) -> (-7, -56)
  line L2 (7, -49.5) -> (7, -56)
  line L3 (-7, -49.5) -> (7, -49.5)
  line L4 (-7, -56) -> (-7, -49.5)
extrude "Extrude9" cut sketch "Front USB-C cable clearance profile" along normal blind 4.2
sketch "PCB 28 x 17 x 1 profile" plane through (0, 0, 0) normal (0, 0, 1) x axis (1, 0, 0)
  line L1 (8.5, -14) -> (-8.5, -14)
  line L2 (8.5, 14) -> (8.5, -14)
  line L3 (-8.5, 14) -> (8.5, 14)
  line L4 (-8.5, -14) -> (-8.5, 14)
extrude "Extrude1" new body sketch "PCB 28 x 17 x 1 profile" along normal blind 1
sketch "Battery and protected output solder holes profile" plane through (0, 0, 0) normal (0, 0, 1) x axis (1, 0, 0)
  circle C1 centre (-6, 8) radius 0.65
  circle C2 centre (6, 8) radius 0.65
  circle C3 centre (-6, 12) radius 0.65
  circle C4 centre (6, 12) radius 0.65
extrude "Extrude2" cut sketch "Battery and protected output solder holes profile" along normal blind 1
work_plane "WorkPlane1" AlongDistance 1 ExtraOffset 0
sketch "Top solder pads profiles" plane through (0, 0, 1) normal (0, 0, 1) x axis (1, 0, 0)
  circle C1 centre (-6, 8) radius 1.3
  circle C2 centre (-6, 8) radius 0.65
  circle C3 centre (6, 8) radius 1.3
  circle C4 centre (6, 8) radius 0.65
  circle C5 centre (-6, 12) radius 1.3
  circle C6 centre (-6, 12) radius 0.65
  circle C7 centre (6, 12) radius 1.3
  circle C8 centre (6, 12) radius 0.65
extrude "Extrude3" new body sketch "Top solder pads profiles" along normal blind 0.05
work_plane "WorkPlane2" AlongDistance -0.05 ExtraOffset 0
sketch "Bottom solder pads profiles" plane through (0, 0, -0.05) normal (0, 0, 1) x axis (1, 0, 0)
  circle C1 centre (-6, 8) radius 1.3
  circle C2 centre (-6, 8) radius 0.65
  circle C3 centre (6, 8) radius 1.3
  circle C4 centre (6, 8) radius 0.65
  circle C5 centre (-6, 12) radius 1.3
  circle C6 centre (-6, 12) radius 0.65
  circle C7 centre (6, 12) radius 1.3
  circle C8 centre (6, 12) radius 0.65
extrude "Extrude4" new body sketch "Bottom solder pads profiles" along normal blind 0.05
work_plane "WorkPlane3" AlongDistance 1 ExtraOffset 0
sketch "USB-C shield profile" plane through (0, 0, 1) normal (0, 0, 1) x axis (1, 0, 0)
  line L1 (4.35, -17) -> (-4.35, -17)
  line L2 (4.35, -10) -> (4.35, -17)
  line L3 (-4.35, -10) -> (4.35, -10)
  line L4 (-4.35, -17) -> (-4.35, -10)
extrude "Extrude5" new body sketch "USB-C shield profile" along normal blind 3.2
work_plane "WorkPlane4" AlongDistance 1.35 ExtraOffset 0
sketch "USB-C open mouth profile" plane through (0, 0, 1.35) normal (0, 0, 1) x axis (1, 0, 0)
  line L1 (3.8, -17.2) -> (-3.8, -17.2)
  line L2 (3.8, -10.7) -> (3.8, -17.2)
  line L3 (-3.8, -10.7) -> (3.8, -10.7)
  line L4 (-3.8, -17.2) -> (-3.8, -10.7)
extrude "Extrude6" cut sketch "USB-C open mouth profile" along normal blind 2.5
work_plane "WorkPlane5" AlongDistance 2.15 ExtraOffset 0
sketch "USB-C contact tongue profile" plane through (0, 0, 2.15) normal (0, 0, 1) x axis (1, 0, 0)
  line L1 (3, -16.7) -> (-3, -16.7)
  line L2 (3, -11.5) -> (3, -16.7)
  line L3 (-3, -11.5) -> (3, -11.5)
  line L4 (-3, -16.7) -> (-3, -11.5)
extrude "Extrude7" new body sketch "USB-C contact tongue profile" along normal blind 0.5
work_plane "WorkPlane6" AlongDistance 2.65 ExtraOffset 0
sketch "USB contacts profiles" plane through (0, 0, 2.65) normal (0, 0, 1) x axis (1, 0, 0)
  line L1 (-2.4, -16.4) -> (-2.6, -16.4)
  line L2 (-2.4, -14.4) -> (-2.4, -16.4)
  line L3 (-2.6, -14.4) -> (-2.4, -14.4)
  line L4 (-2.6, -16.4) -> (-2.6, -14.4)
  line L5 (-1.93, -16.4) -> (-2.13, -16.4)
  line L6 (-1.93, -14.4) -> (-1.93, -16.4)
  line L7 (-2.13, -14.4) -> (-1.93, -14.4)
  line L8 (-2.13, -16.4) -> (-2.13, -14.4)
  line L9 (-1.46, -16.4) -> (-1.66, -16.4)
  line L10 (-1.46, -14.4) -> (-1.46, -16.4)
  line L11 (-1.66, -14.4) -> (-1.46, -14.4)
  line L12 (-1.66, -16.4) -> (-1.66, -14.4)
  line L13 (-0.99, -16.4) -> (-1.19, -16.4)
  line L14 (-0.99, -14.4) -> (-0.99, -16.4)
  line L15 (-1.19, -14.4) -> (-0.99, -14.4)
  line L16 (-1.19, -16.4) -> (-1.19, -14.4)
  line L17 (-0.52, -16.4) -> (-0.72, -16.4)
  line L18 (-0.52, -14.4) -> (-0.52, -16.4)
  line L19 (-0.72, -14.4) -> (-0.52, -14.4)
  line L20 (-0.72, -16.4) -> (-0.72, -14.4)
  line L21 (-0.05, -16.4) -> (-0.25, -16.4)
  line L22 (-0.05, -14.4) -> (-0.05, -16.4)
  line L23 (-0.25, -14.4) -> (-0.05, -14.4)
  line L24 (-0.25, -16.4) -> (-0.25, -14.4)
  line L25 (0.42, -16.4) -> (0.22, -16.4)
  line L26 (0.42, -14.4) -> (0.42, -16.4)
  line L27 (0.22, -14.4) -> (0.42, -14.4)
  line L28 (0.22, -16.4) -> (0.22, -14.4)
  line L29 (0.89, -16.4) -> (0.69, -16.4)
  line L30 (0.89, -14.4) -> (0.89, -16.4)
  line L31 (0.69, -14.4) -> (0.89, -14.4)
  line L32 (0.69, -16.4) -> (0.69, -14.4)
  line L33 (1.36, -16.4) -> (1.16, -16.4)
  line L34 (1.36, -14.4) -> (1.36, -16.4)
  line L35 (1.16, -14.4) -> (1.36, -14.4)
  line L36 (1.16, -16.4) -> (1.16, -14.4)
  line L37 (1.83, -16.4) -> (1.63, -16.4)
  line L38 (1.83, -14.4) -> (1.83, -16.4)
  line L39 (1.63, -14.4) -> (1.83, -14.4)
  line L40 (1.63, -16.4) -> (1.63, -14.4)
  line L41 (2.3, -16.4) -> (2.1, -16.4)
  line L42 (2.3, -14.4) -> (2.3, -16.4)
  line L43 (2.1, -14.4) -> (2.3, -14.4)
  line L44 (2.1, -16.4) -> (2.1, -14.4)
  line L45 (2.77, -16.4) -> (2.57, -16.4)
  line L46 (2.77, -14.4) -> (2.77, -16.4)
  line L47 (2.57, -14.4) -> (2.77, -14.4)
  line L48 (2.57, -16.4) -> (2.57, -14.4)
extrude "Extrude8" new body sketch "USB contacts profiles" along normal blind 0.04
work_plane "WorkPlane7" AlongDistance 1.25 ExtraOffset 0
sketch "TP4056 SOP8 profile" plane through (0, 0, 1.25) normal (0, 0, 1) x axis (1, 0, 0)
  line L1 (1.95, -5.9) -> (-1.95, -5.9)
  line L2 (1.95, -0.9) -> (1.95, -5.9)
  line L3 (-1.95, -0.9) -> (1.95, -0.9)
  line L4 (-1.95, -5.9) -> (-1.95, -0.9)
extrude "Extrude9" new body sketch "TP4056 SOP8 profile" along normal blind 1.65
work_plane "WorkPlane8" AlongDistance 1.04 ExtraOffset 0
sketch "TP4056 SOP8 leads profiles" plane through (0, 0, 1.04) normal (0, 0, 1) x axis (1, 0, 0)
  line L1 (-1.95, -5.515) -> (-2.95, -5.515)
  line L2 (-1.95, -5.095) -> (-1.95, -5.515)
  line L3 (-2.95, -5.095) -> (-1.95, -5.095)
  line L4 (-2.95, -5.515) -> (-2.95, -5.095)
  line L5 (-1.95, -4.245) -> (-2.95, -4.245)
  line L6 (-1.95, -3.825) -> (-1.95, -4.245)
  line L7 (-2.95, -3.825) -> (-1.95, -3.825)
  line L8 (-2.95, -4.245) -> (-2.95, -3.825)
  line L9 (-1.95, -2.975) -> (-2.95, -2.975)
  line L10 (-1.95, -2.555) -> (-1.95, -2.975)
  line L11 (-2.95, -2.555) -> (-1.95, -2.555)
  line L12 (-2.95, -2.975) -> (-2.95, -2.555)
  line L13 (-1.95, -1.705) -> (-2.95, -1.705)
  line L14 (-1.95, -1.285) -> (-1.95, -1.705)
  line L15 (-2.95, -1.285) -> (-1.95, -1.285)
  line L16 (-2.95, -1.705) -> (-2.95, -1.285)
  line L17 (2.95, -5.515) -> (1.95, -5.515)
  line L18 (2.95, -5.095) -> (2.95, -5.515)
  line L19 (1.95, -5.095) -> (2.95, -5.095)
  line L20 (1.95, -5.515) -> (1.95, -5.095)
  line L21 (2.95, -4.245) -> (1.95, -4.245)
  line L22 (2.95, -3.825) -> (2.95, -4.245)
  line L23 (1.95, -3.825) -> (2.95, -3.825)
  line L24 (1.95, -4.245) -> (1.95, -3.825)
  line L25 (2.95, -2.975) -> (1.95, -2.975)
  line L26 (2.95, -2.555) -> (2.95, -2.975)
  line L27 (1.95, -2.555) -> (2.95, -2.555)
  line L28 (1.95, -2.975) -> (1.95, -2.555)
  line L29 (2.95, -1.705) -> (1.95, -1.705)
  line L30 (2.95, -1.285) -> (2.95, -1.705)
  line L31 (1.95, -1.285) -> (2.95, -1.285)
  line L32 (1.95, -1.705) -> (1.95, -1.285)
extrude "Extrude10" new body sketch "TP4056 SOP8 leads profiles" along normal blind 0.45
work_plane "WorkPlane9" AlongDistance 1.25 ExtraOffset 0
sketch "8205A dual MOSFET profile" plane through (0, 0, 1.25) normal (0, 0, 1) x axis (1, 0, 0)
  line L1 (1.95, 2) -> (-1.95, 2)
  line L2 (1.95, 7) -> (1.95, 2)
  line L3 (-1.95, 7) -> (1.95, 7)
  line L4 (-1.95, 2) -> (-1.95, 7)
extrude "Extrude11" new body sketch "8205A dual MOSFET profile" along normal blind 1.4
work_plane "WorkPlane10" AlongDistance 1.04 ExtraOffset 0
sketch "8205A dual MOSFET leads profiles" plane through (0, 0, 1.04) normal (0, 0, 1) x axis (1, 0, 0)
  line L1 (-1.95, 2.385) -> (-2.95, 2.385)
  line L2 (-1.95, 2.805) -> (-1.95, 2.385)
  line L3 (-2.95, 2.805) -> (-1.95, 2.805)
  line L4 (-2.95, 2.385) -> (-2.95, 2.805)
  line L5 (-1.95, 3.655) -> (-2.95, 3.655)
  line L6 (-1.95, 4.075) -> (-1.95, 3.655)
  line L7 (-2.95, 4.075) -> (-1.95, 4.075)
  line L8 (-2.95, 3.655) -> (-2.95, 4.075)
  line L9 (-1.95, 4.925) -> (-2.95, 4.925)
  line L10 (-1.95, 5.345) -> (-1.95, 4.925)
  line L11 (-2.95, 5.345) -> (-1.95, 5.345)
  line L12 (-2.95, 4.925) -> (-2.95, 5.345)
  line L13 (-1.95, 6.195) -> (-2.95, 6.195)
  line L14 (-1.95, 6.615) -> (-1.95, 6.195)
  line L15 (-2.95, 6.615) -> (-1.95, 6.615)
  line L16 (-2.95, 6.195) -> (-2.95, 6.615)
  line L17 (2.95, 2.385) -> (1.95, 2.385)
  line L18 (2.95, 2.805) -> (2.95, 2.385)
  line L19 (1.95, 2.805) -> (2.95, 2.805)
  line L20 (1.95, 2.385) -> (1.95, 2.805)
  line L21 (2.95, 3.655) -> (1.95, 3.655)
  line L22 (2.95, 4.075) -> (2.95, 3.655)
  line L23 (1.95, 4.075) -> (2.95, 4.075)
  line L24 (1.95, 3.655) -> (1.95, 4.075)
  line L25 (2.95, 4.925) -> (1.95, 4.925)
  line L26 (2.95, 5.345) -> (2.95, 4.925)
  line L27 (1.95, 5.345) -> (2.95, 5.345)
  line L28 (1.95, 4.925) -> (1.95, 5.345)
  line L29 (2.95, 6.195) -> (1.95, 6.195)
  line L30 (2.95, 6.615) -> (2.95, 6.195)
  line L31 (1.95, 6.615) -> (2.95, 6.615)
  line L32 (1.95, 6.195) -> (1.95, 6.615)
extrude "Extrude12" new body sketch "8205A dual MOSFET leads profiles" along normal blind 0.45
work_plane "WorkPlane11" AlongDistance 1.25 ExtraOffset 0
sketch "DW01A SOT23-6 profile" plane through (0, 0, 1.25) normal (0, 0, 1) x axis (1, 0, 0)
  line L1 (6.3, 0.55) -> (4.5, 0.55)
  line L2 (6.3, 3.45) -> (6.3, 0.55)
  line L3 (4.5, 3.45) -> (6.3, 3.45)
  line L4 (4.5, 0.55) -> (4.5, 3.45)
extrude "Extrude13" new body sketch "DW01A SOT23-6 profile" along normal blind 1.1
work_plane "WorkPlane12" AlongDistance 1.04 ExtraOffset 0
sketch "DW01A SOT23-6 leads profiles" plane through (0, 0, 1.04) normal (0, 0, 1) x axis (1, 0, 0)
  line L1 (4.5, 0.84) -> (3.5, 0.84)
  line L2 (4.5, 1.26) -> (4.5, 0.84)
  line L3 (3.5, 1.26) -> (4.5, 1.26)
  line L4 (3.5, 0.84) -> (3.5, 1.26)
  line L5 (4.5, 1.79) -> (3.5, 1.79)
  line L6 (4.5, 2.21) -> (4.5, 1.79)
  line L7 (3.5, 2.21) -> (4.5, 2.21)
  line L8 (3.5, 1.79) -> (3.5, 2.21)
  line L9 (4.5, 2.74) -> (3.5, 2.74)
  line L10 (4.5, 3.16) -> (4.5, 2.74)
  line L11 (3.5, 3.16) -> (4.5, 3.16)
  line L12 (3.5, 2.74) -> (3.5, 3.16)
  line L13 (7.3, 0.84) -> (6.3, 0.84)
  line L14 (7.3, 1.26) -> (7.3, 0.84)
  line L15 (6.3, 1.26) -> (7.3, 1.26)
  line L16 (6.3, 0.84) -> (6.3, 1.26)
  line L17 (7.3, 1.79) -> (6.3, 1.79)
  line L18 (7.3, 2.21) -> (7.3, 1.79)
  line L19 (6.3, 2.21) -> (7.3, 2.21)
  line L20 (6.3, 1.79) -> (6.3, 2.21)
  line L21 (7.3, 2.74) -> (6.3, 2.74)
  line L22 (7.3, 3.16) -> (7.3, 2.74)
  line L23 (6.3, 3.16) -> (7.3, 3.16)
  line L24 (6.3, 2.74) -> (6.3, 3.16)
extrude "Extrude14" new body sketch "DW01A SOT23-6 leads profiles" along normal blind 0.45
work_plane "WorkPlane13" AlongDistance 1.04 ExtraOffset 0
sketch "Programming and bias resistors profiles" plane through (0, 0, 1.04) normal (0, 0, 1) x axis (1, 0, 0)
  line L1 (-5.9, -4) -> (-6.9, -4)
  line L2 (-5.9, -2) -> (-5.9, -4)
  line L3 (-6.9, -2) -> (-5.9, -2)
  line L4 (-6.9, -4) -> (-6.9, -2)
  line L5 (-5.9, 1) -> (-6.9, 1)
  line L6 (-5.9, 2.8) -> (-5.9, 1)
  line L7 (-6.9, 2.8) -> (-5.9, 2.8)
  line L8 (-6.9, 1) -> (-6.9, 2.8)
  line L9 (6.3, -5.5) -> (5.3, -5.5)
  line L10 (6.3, -3.5) -> (6.3, -5.5)
  line L11 (5.3, -3.5) -> (6.3, -3.5)
  line L12 (5.3, -5.5) -> (5.3, -3.5)
extrude "Extrude15" new body sketch "Programming and bias resistors profiles" along normal blind 0.55
work_plane "WorkPlane14" AlongDistance 1.04 ExtraOffset 0
sketch "Ceramic capacitors profiles" plane through (0, 0, 1.04) normal (0, 0, 1) x axis (1, 0, 0)
  line L1 (-5.3, -8.5) -> (-6.8, -8.5)
  line L2 (-5.3, -6.2) -> (-5.3, -8.5)
  line L3 (-6.8, -6.2) -> (-5.3, -6.2)
  line L4 (-6.8, -8.5) -> (-6.8, -6.2)
  line L5 (6.8, -8.5) -> (5.3, -8.5)
  line L6 (6.8, -6.2) -> (6.8, -8.5)
  line L7 (5.3, -6.2) -> (6.8, -6.2)
  line L8 (5.3, -8.5) -> (5.3, -6.2)
extrude "Extrude16" new body sketch "Ceramic capacitors profiles" along normal blind 0.8
work_plane "WorkPlane15" AlongDistance 1.04 ExtraOffset 0
sketch "Charge indicator profile" plane through (0, 0, 1.04) normal (0, 0, 1) x axis (1, 0, 0)
  line L1 (-1.7, -8.5) -> (-3.5, -8.5)
  line L2 (-1.7, -7.3) -> (-1.7, -8.5)
  line L3 (-3.5, -7.3) -> (-1.7, -7.3)
  line L4 (-3.5, -8.5) -> (-3.5, -7.3)
extrude "Extrude17" new body sketch "Charge indicator profile" along normal blind 0.7
work_plane "WorkPlane16" AlongDistance 1.04 ExtraOffset 0
sketch "Full indicator profile" plane through (0, 0, 1.04) normal (0, 0, 1) x axis (1, 0, 0)
  line L1 (3.5, -8.5) -> (1.7, -8.5)
  line L2 (3.5, -7.3) -> (3.5, -8.5)
  line L3 (1.7, -7.3) -> (3.5, -7.3)
  line L4 (1.7, -8.5) -> (1.7, -7.3)
extrude "Extrude18" new body sketch "Full indicator profile" along normal blind 0.7
work_plane "WorkPlane17" AlongDistance 2.9 ExtraOffset 0
sketch "4056 marking" plane through (0, 0, 2.9) normal (0, 0, 1) x axis (1, 0, 0)
  dimension "d606" = 0.85
  dimension "d607" = "'4056'"
extrude "Extrude19" new body sketch "4056 marking" along normal blind 0.02
work_plane "WorkPlane18" AlongDistance 1 ExtraOffset 0
sketch "1S marking" plane through (0, 0, 1) normal (0, 0, 1) x axis (1, 0, 0)
  dimension "d612" = 1.1
  dimension "d613" = "'1S'"
extrude "Extrude20" new body sketch "1S marking" along normal blind 0.025
work_plane "WorkPlane1" AlongDistance 4.8 ExtraOffset 0
sketch "Insulating mounting tape profile" plane through (0, 0, 4.8) normal (0, 0, 1) x axis (1, 0, 0)
  line L1 (6, -49.8) -> (-6, -49.8)
  line L2 (6, -47.5) -> (6, -49.8)
  line L3 (-6, -47.5) -> (6, -47.5)
  line L4 (-6, -49.8) -> (-6, -47.5)
extrude "Extrude1" new body sketch "Insulating mounting tape profile" along normal blind 1.3
work_plane "WorkPlane2" AlongDistance 4.8 ExtraOffset 0
sketch "Insulating mounting tape profile (1)" plane through (0, 0, 4.8) normal (0, 0, 1) x axis (1, 0, 0)
  line L1 (6, -29.3) -> (-6, -29.3)
  line L2 (6, -27) -> (6, -29.3)
  line L3 (-6, -27) -> (6, -27)
  line L4 (-6, -29.3) -> (-6, -27)
extrude "Extrude2" new body sketch "Insulating mounting tape profile (1)" along normal blind 1.3
work_plane "WorkPlane1" AlongDistance -3.2 ExtraOffset 0
sketch "M3 x8 shank profile" plane through (0, 0, -3.2) normal (0, 0, 1) x axis (1, 0, 0)
  circle C1 centre (-12, -45) radius 1.5
extrude "Extrude1" new body sketch "M3 x8 shank profile" along normal blind 8
work_plane "WorkPlane2" AlongDistance 4.8 ExtraOffset 0
sketch "M3 button head profile" plane through (0, 0, 4.8) normal (0, 0, 1) x axis (1, 0, 0)
  circle C1 centre (-12, -45) radius 2.7
extrude "Extrude2" new body sketch "M3 button head profile" along normal blind 2.2
work_plane "WorkPlane3" AlongDistance 5.9 ExtraOffset 0
sketch "M3 hex drive" plane through (0, 0, 5.9) normal (0, 0, 1) x axis (1, 0, 0)
  line L1 (-11.3, -43.7876) -> (-10.6, -45)
  line L2 (-12.7, -43.7876) -> (-11.3, -43.7876)
  line L3 (-13.4, -45) -> (-12.7, -43.7876)
  line L4 (-12.7, -46.2124) -> (-13.4, -45)
  line L5 (-11.3, -46.2124) -> (-12.7, -46.2124)
  line L6 (-10.6, -45) -> (-11.3, -46.2124)
extrude "Extrude3" cut sketch "M3 hex drive" along normal blind 1.1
